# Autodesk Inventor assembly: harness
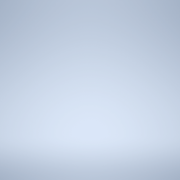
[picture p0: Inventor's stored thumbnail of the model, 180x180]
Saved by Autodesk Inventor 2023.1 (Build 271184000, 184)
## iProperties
Part Number: harness
Document SubType Name: Assembly
Created: 2002-07
Designer: invbi
HarnessSettings: <HarnessSettings><Defaults><Segments><Diameter value="0.200 in" fromwires="True"/><Offset value="0.100 in"/><ColorStyle value="Blue"/><BendRadius value="19" fro
Control State: 0
Master: False
Checked Out: False
Shininess: 64.0
Length Units: 11272
Angle Units: 11279
Time Units: 11290
Mass Units: 11286
Length Display Precision: 3
Angle Display Precision: 2
Compacted: True
Density: 0.0
Volumn: 0.0
Area: 0.0
PropertySet Name: Model Information
HarnessSettings: <HarnessSettings><Defaults><Segments><Diameter value="0.200 in" fromwires="True"/><Offset value="0.100 in"/><ColorStyle value="Blue"/><RoundUp value=""/><BendRa
Author: invbi
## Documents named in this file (1)
- M:\AUTOBUILD\INV.Official.R1\Application\App\Design Data\Cable & Harness\harness.iam
